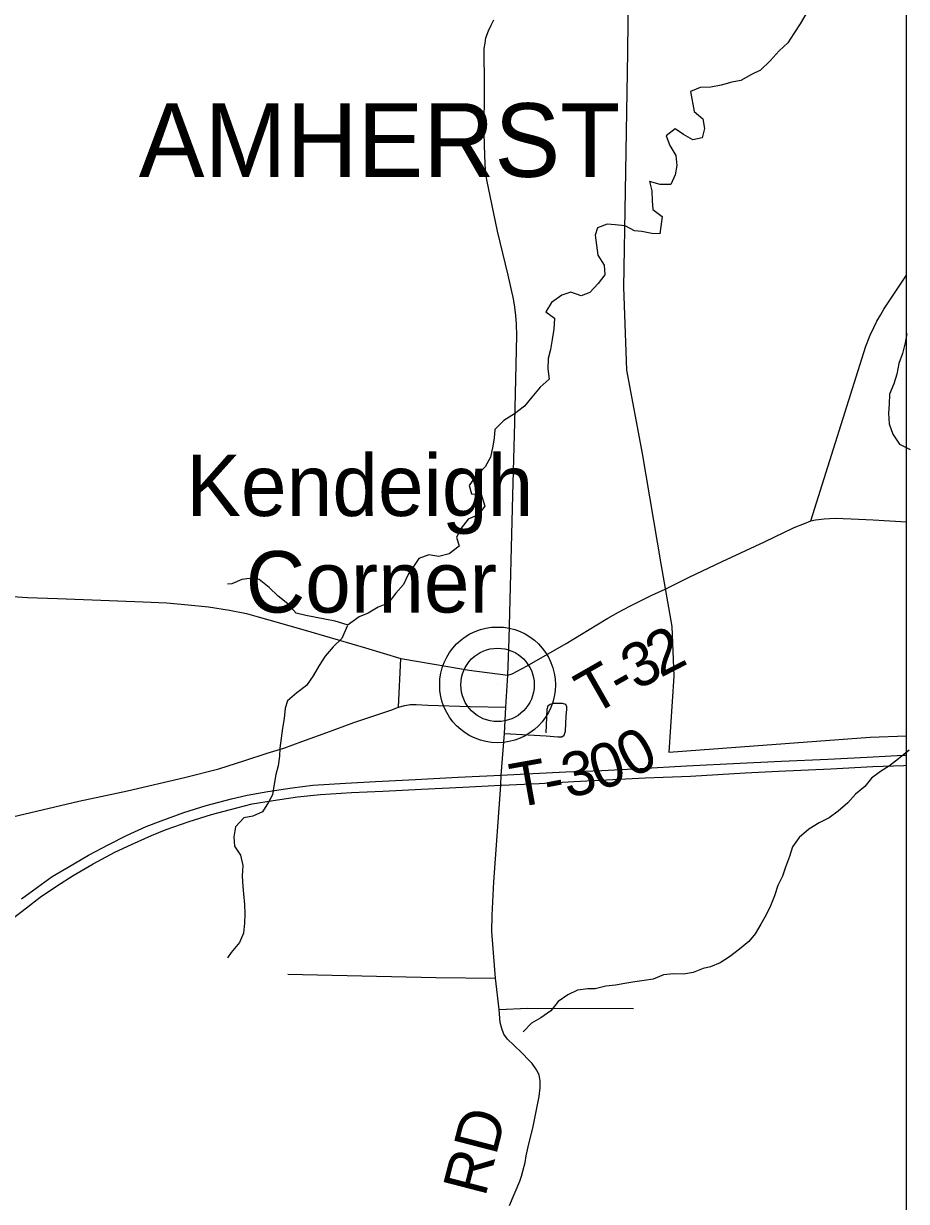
# Model space of a CAD drawing. Extents: x 0 to 34, y 0 to 22.
# Drawn here: x 12.978 to 14.113, y 6.981 to 8.496 of the extents above; entities that cross this region are included whole.
import ezdxf

# ---------------------------------------------------------------- set-up
doc = ezdxf.new("R2010")
doc.units = 0
for name, color, linetype in [('GM_X_Corporation', 7, 'Continuous'), ('GM_X_Corporation_Text', 7, 'Continuous'), ('GM_X_County_Road', 7, 'Continuous'), ('GM_X_County_Road_Text', 7, 'Continuous'), ('GM_X_Interstate_Route', 7, 'Continuous'), ('GM_X_Minor_River', 7, 'Continuous'), ('GM_X_Rail_Line', 7, 'Continuous'), ('GM_X_Township_Road', 7, 'Continuous'), ('GM_X_Township_Road_Text', 7, 'Continuous'), ('GM_X_Unincorporated', 7, 'Continuous'), ('GM_X_Unincorporated_Location', 7, 'Continuous'), ('GM_X_Unincorporated_Text', 7, 'Continuous'), ('SH_Cut_Line', 7, 'Continuous')]:
    doc.layers.add(name, color=color, linetype=linetype)

msp = doc.modelspace()

# ---------------------------------------------------------------- linework, layer by layer
at = {"layer": 'GM_X_Corporation'}
msp.add_lwpolyline([(13.756, 8.5811), (13.7547, 8.4582), (13.752, 8.2803), (13.7496, 8.1567), (13.7537, 8.0502), (13.7737, 7.9429), (13.7976, 7.801), (13.8118, 7.7204), (13.8142, 7.6569), (13.808, 7.5592), (14.0669, 7.5781), (14.1135, 7.5799), (14.1135, 10.1047)], dxfattribs=at)
at = {"layer": 'GM_X_County_Road'}
msp.add_line((13.5982, 7.6167), (13.6011, 7.658), dxfattribs=at)
for points in [[(13.6011, 7.658), (13.6026, 7.7047), (13.6072, 7.889), (13.61, 7.9829), (13.6124, 8.0948), (13.6122, 8.109), (13.6114, 8.1203), (13.61, 8.1309), (13.6082, 8.1419), (13.6013, 8.1722), (13.5878, 8.2287), (13.5741, 8.2948), (13.5723, 8.3066), (13.5714, 8.3258), (13.5706, 8.3541), (13.5709, 8.415), (13.5706, 8.4634), (13.5716, 8.4703), (13.5728, 8.4772), (13.576, 8.4863), (13.5795, 8.4937), (13.5827, 8.5003)], [(13.9907, 7.8565), (14.0613, 8.0808), (14.067, 8.0951), (14.0715, 8.1049), (14.0756, 8.1132), (14.0799, 8.1206), (14.0844, 8.1283), (14.1135, 8.172)], [(13.603, 6.9764), (13.6163, 7.0074), (13.6187, 7.0138), (13.6204, 7.0203), (13.623, 7.0317), (13.6247, 7.0403), (13.6271, 7.0516), (13.6333, 7.0778), (13.641, 7.1162), (13.6426, 7.1276), (13.6424, 7.1367), (13.641, 7.1441), (13.6378, 7.1507), (13.632, 7.1588), (13.6281, 7.1631), (13.6194, 7.1719), (13.6087, 7.1823), (13.6006, 7.1902), (13.5957, 7.1966), (13.593, 7.2038), (13.5912, 7.2114), (13.5897, 7.2281), (13.5851, 7.2683), (13.5805, 7.3284), (13.5809, 7.3496), (13.5831, 7.3922), (13.5917, 7.5164), (13.5923, 7.5294), (13.5967, 7.583), (13.5982, 7.6167)]]:
    msp.add_lwpolyline(points, dxfattribs=at)
at = {"layer": 'GM_X_Interstate_Route'}
for points in [[(12.9756, 7.3703), (12.996, 7.3856), (13.0152, 7.3993), (13.0354, 7.4111), (13.0617, 7.4266), (13.0877, 7.4404), (13.1105, 7.4519), (13.136, 7.4634), (13.1551, 7.4708), (13.1843, 7.4814), (13.2131, 7.4904), (13.2457, 7.499), (13.2656, 7.5039), (13.2924, 7.5085), (13.3237, 7.5133), (13.35, 7.5164), (13.3923, 7.5192), (13.4308, 7.5212), (13.4821, 7.5238), (13.5366, 7.5268), (13.5923, 7.5294), (13.633, 7.5314), (13.6757, 7.5337), (13.7218, 7.5355), (13.7712, 7.538), (13.8307, 7.5413), (13.8996, 7.5447), (13.9529, 7.5473), (14.0125, 7.5501), (14.0628, 7.5528), (14.1092, 7.5551), (14.1135, 7.5553)], [(13.5927, 7.5165), (13.6414, 7.5189), (13.6858, 7.5212), (13.7277, 7.5235), (13.7774, 7.526), (13.8358, 7.5283), (13.9059, 7.5324), (13.949, 7.5344), (14.0161, 7.5375), (14.0702, 7.5405), (14.1099, 7.5419), (14.1135, 7.5421)], [(12.9582, 7.3403), (12.9822, 7.3588), (12.9997, 7.3727), (13.0219, 7.3878), (13.042, 7.4005), (13.0676, 7.4156), (13.0956, 7.4306), (13.1171, 7.4404), (13.1426, 7.452), (13.1617, 7.4594), (13.191, 7.4699), (13.2198, 7.4789), (13.2524, 7.4875), (13.2723, 7.4924), (13.2991, 7.497), (13.3303, 7.5018), (13.3601, 7.5046), (13.3999, 7.5071), (13.4402, 7.5087), (13.4899, 7.5115), (13.5432, 7.514), (13.5917, 7.5164), (13.5927, 7.5165)]]:
    msp.add_lwpolyline(points, dxfattribs=at)
at = {"layer": 'GM_X_Minor_River'}
for points in [[(13.9842, 8.5076), (13.9767, 8.4954), (13.9688, 8.4828), (13.961, 8.4709), (13.95, 8.4606), (13.9384, 8.4476), (13.9259, 8.4357), (13.9142, 8.4303), (13.9006, 8.4226), (13.8888, 8.4202), (13.8751, 8.4163), (13.8619, 8.4139), (13.8482, 8.4134), (13.8357, 8.4084), (13.8405, 8.3826), (13.8516, 8.3732), (13.854, 8.3607), (13.8506, 8.3489), (13.8389, 8.3461), (13.8267, 8.3532), (13.8159, 8.3604), (13.8046, 8.3512), (13.8093, 8.339), (13.817, 8.3262), (13.8183, 8.3133), (13.8161, 8.3011), (13.8105, 8.2889), (13.7968, 8.2888), (13.7831, 8.2925), (13.7862, 8.2807), (13.7863, 8.2678), (13.7872, 8.2564), (13.7995, 8.2477), (13.7977, 8.2348), (13.7962, 8.2253), (13.786, 8.2256), (13.7734, 8.2285), (13.7639, 8.2292), (13.7517, 8.2356), (13.7391, 8.237), (13.7288, 8.2377), (13.7163, 8.233), (13.713, 8.2235), (13.715, 8.2106), (13.7166, 8.1981), (13.7247, 8.1852), (13.7256, 8.1727), (13.717, 8.1616), (13.7064, 8.1501), (13.695, 8.1458), (13.6821, 8.1503), (13.6703, 8.1464), (13.6571, 8.1372), (13.6496, 8.125), (13.6611, 8.1167), (13.6601, 8.1026), (13.6579, 8.0893), (13.6557, 8.0767), (13.6528, 8.0649), (13.6525, 8.0516), (13.6542, 8.0383), (13.6425, 8.028), (13.6319, 8.0154), (13.6222, 8.0039), (13.6097, 7.9939), (13.5957, 7.9854), (13.5844, 7.974), (13.5834, 7.9629), (13.5816, 7.9523), (13.5786, 7.9382), (13.5719, 7.926), (13.5598, 7.9141), (13.5512, 7.9019), (13.554, 7.8909), (13.5665, 7.8906), (13.5712, 7.8754), (13.5626, 7.8639), (13.5501, 7.8585), (13.541, 7.8471), (13.5351, 7.8352), (13.5382, 7.8238), (13.5254, 7.8139), (13.5121, 7.8107), (13.4992, 7.8125), (13.4863, 7.8079), (13.4728, 7.7876), (13.4668, 7.7746), (13.457, 7.7636), (13.4472, 7.7506), (13.434, 7.7455), (13.4215, 7.7378)], [(14.114, 8.0974), (14.1118, 8.0852), (14.1082, 8.0715), (14.1037, 8.0585), (14.1012, 8.0448), (14.0971, 8.0326), (14.0915, 8.0193), (14.0913, 8.0064), (14.0906, 7.9946), (14.0911, 7.9809), (14.0958, 7.968), (14.1046, 7.9551), (14.1184, 7.948)], [(13.3945, 7.7228), (13.379, 7.7272), (13.3657, 7.7298), (13.3413, 7.7349), (13.3287, 7.7379), (13.318, 7.7499), (13.3057, 7.7594), (13.2939, 7.7707), (13.2812, 7.7808), (13.2687, 7.7823), (13.2588, 7.781), (13.2459, 7.7752), (13.2404, 7.7749)], [(13.4215, 7.7378), (13.4098, 7.7328), (13.3942, 7.7217)], [(13.3942, 7.7211), (13.3876, 7.7052), (13.3763, 7.6945), (13.3661, 7.6823), (13.3582, 7.6704), (13.3507, 7.6571), (13.3421, 7.6448), (13.3296, 7.6352), (13.3176, 7.6249), (13.3146, 7.6154), (13.3132, 7.6024), (13.311, 7.5899), (13.3096, 7.5769), (13.3078, 7.564), (13.3072, 7.5537), (13.3054, 7.5416), (13.3028, 7.5301), (13.3003, 7.518), (13.2985, 7.5043), (13.2932, 7.4947), (13.2854, 7.4825), (13.2732, 7.4767), (13.2615, 7.4747), (13.2506, 7.4632), (13.2488, 7.4503), (13.2496, 7.4381), (13.2573, 7.4264), (13.2601, 7.4135), (13.2591, 7.3998), (13.26, 7.3865), (13.2612, 7.377), (13.2625, 7.3633), (13.2626, 7.3512), (13.2623, 7.339), (13.2609, 7.3265), (13.256, 7.3143), (13.2451, 7.3016), (13.2404, 7.2947)], [(14.1168, 7.5615), (14.1032, 7.5503), (14.0915, 7.5415), (14.0802, 7.5342), (14.0685, 7.5257), (14.0598, 7.515), (14.0478, 7.5051), (14.038, 7.494)], [(14.038, 7.494), (14.0255, 7.4832), (14.0142, 7.4748), (14.0013, 7.4682), (13.9881, 7.4601), (13.9756, 7.4494), (13.967, 7.4375), (13.9629, 7.425), (13.9581, 7.4112), (13.954, 7.3998), (13.9481, 7.3876), (13.944, 7.3743), (13.9388, 7.3613), (13.9332, 7.3498), (13.9264, 7.338), (13.9189, 7.3254), (13.9107, 7.3155), (13.8986, 7.3059), (13.8858, 7.2959), (13.874, 7.2882), (13.8615, 7.2832), (13.8521, 7.2808), (13.8392, 7.2758), (13.8266, 7.2738), (13.8141, 7.2741), (13.8012, 7.2728), (13.7879, 7.2674), (13.7762, 7.2654), (13.7644, 7.2638), (13.7515, 7.2618), (13.7393, 7.2594), (13.7268, 7.2582), (13.7131, 7.255), (13.7036, 7.2546), (13.6903, 7.253), (13.6782, 7.2472), (13.6658, 7.2387), (13.6564, 7.2265), (13.6435, 7.2173), (13.6314, 7.2107), (13.6205, 7.1996)]]:
    msp.add_lwpolyline(points, dxfattribs=at)
at = {"layer": 'GM_X_Rail_Line'}
msp.add_lwpolyline([(14.1135, 5.8645), (14.1135, 10.4074), (12.9952, 10.4123), (12.9843, 9.8218), (12.975, 9.4666), (12.9697, 9.2637), (12.9695, 9.2552), (12.9694, 9.2509), (12.9542, 8.6724), (12.9304, 7.7644), (12.9222, 7.4711), (12.9186, 7.3231), (12.9183, 7.3117), (12.9181, 7.3048), (12.8807, 5.8723), (13.2678, 5.8695), (13.384, 5.8688), (13.5036, 5.8681)], close=True, dxfattribs=at)
at = {"layer": 'GM_X_Township_Road'}
for p, q in [((13.4605, 7.6167), (13.4632, 7.6796)), ((13.5982, 7.6167), (13.6011, 7.658))]:
    msp.add_line(p, q, dxfattribs=at)
for points in [[(13.8195, 7.7767), (13.8339, 7.7838), (13.8764, 7.804), (13.931, 7.8295), (13.9693, 7.8477), (13.9823, 7.8531), (13.9907, 7.8565), (13.9966, 7.8578), (14.0076, 7.8588), (14.0219, 7.8598), (14.0425, 7.859), (14.0708, 7.8576), (14.1135, 7.8549)], [(13.6011, 7.658), (13.6065, 7.6596), (13.6257, 7.6698), (13.6758, 7.6988), (13.7152, 7.7226), (13.7294, 7.7312), (13.7434, 7.7388), (13.7579, 7.7465), (13.7854, 7.7602), (13.8034, 7.7687), (13.8195, 7.7767)], [(12.9391, 7.762), (12.94, 7.7618), (12.9522, 7.7601), (12.9831, 7.758), (13.0217, 7.7565), (13.0775, 7.7544), (13.1322, 7.7524), (13.1623, 7.7508), (13.1899, 7.7486), (13.216, 7.7458), (13.2429, 7.7415), (13.2649, 7.7372), (13.2797, 7.7331), (13.3074, 7.7252), (13.3477, 7.7138), (13.4179, 7.6933), (13.4632, 7.6796), (13.5062, 7.672), (13.551, 7.6644), (13.6011, 7.658)], [(12.9361, 7.4714), (12.9399, 7.4719), (12.9638, 7.4761), (13.0493, 7.496), (13.1117, 7.5095), (13.185, 7.5265), (13.2292, 7.5378), (13.2629, 7.5481), (13.2916, 7.5577), (13.3128, 7.5643), (13.3359, 7.5729), (13.3681, 7.5842), (13.403, 7.597), (13.4504, 7.613), (13.4605, 7.6167), (13.4684, 7.6189), (13.4755, 7.6201), (13.4829, 7.6201), (13.4981, 7.6196), (13.5524, 7.6177), (13.5982, 7.6167)], [(13.5967, 7.583), (13.65, 7.5801), (13.6653, 7.5786), (13.6704, 7.5788), (13.6733, 7.5808), (13.6751, 7.586), (13.6758, 7.6054), (13.6766, 7.6145), (13.6766, 7.6174), (13.6753, 7.6204), (13.6714, 7.6214), (13.6596, 7.6214), (13.6554, 7.6201), (13.6522, 7.6182), (13.6512, 7.6137), (13.6498, 7.5838)], [(13.3182, 7.2735), (13.5082, 7.2695), (13.5851, 7.2683)], [(13.5897, 7.2281), (13.6261, 7.2301), (13.7627, 7.2296)]]:
    msp.add_lwpolyline(points, dxfattribs=at)
at = {"layer": 'GM_X_Unincorporated'}
for radius in [0.0744, 0.0472]:
    msp.add_circle((13.5877, 7.6455), radius, dxfattribs=at)
at = {"layer": 'GM_X_Unincorporated_Location'}
msp.add_line((13.5877, 7.6455), (13.5877, 7.6455), dxfattribs=at)
at = {"layer": 'SH_Cut_Line'}
msp.add_lwpolyline([(8.8581, 3.6647), (14.1135, 3.6647), (14.1135, 10.4647), (8.6408, 10.4647)], dxfattribs=at)

# ---------------------------------------------------------------- texts
at = {"layer": 'GM_X_Corporation_Text'}
msp.add_text('AMHERST', height=0.0947, rotation=0, dxfattribs=at).set_placement((13.1264, 8.2985))
at = {"layer": 'GM_X_County_Road_Text'}
msp.add_text('RD', height=0.05682, rotation=75.4845, dxfattribs=at).set_placement((13.5718, 6.9862))
at = {"layer": 'GM_X_Township_Road_Text'}
for s, rotation, p in [('2', 27.1981, (13.797, 7.6543)), ('3', 28.49, (13.7666, 7.6378)), ('T', 29.7693, (13.7096, 7.6054)), ('-', 29.3382, (13.7464, 7.6265)), ('0', 28.7259, (13.7606, 7.5245)), ('0', 18.1823, (13.7169, 7.5091)), ('3', 12.8914, (13.6773, 7.4997)), ('T', 10.1761, (13.6096, 7.4873)), ('-', 10.7765, (13.6521, 7.4949))]:
    msp.add_text(s, height=0.0568, rotation=rotation, dxfattribs=at).set_placement(p)
at = {"layer": 'GM_X_Unincorporated_Text'}
for s, p in [('Kendeigh', (13.1873, 7.8626)), ('Corner', (13.264, 7.7385))]:
    msp.add_text(s, height=0.07898, rotation=0, dxfattribs=at).set_placement(p)

doc.saveas('drawing.dxf')
